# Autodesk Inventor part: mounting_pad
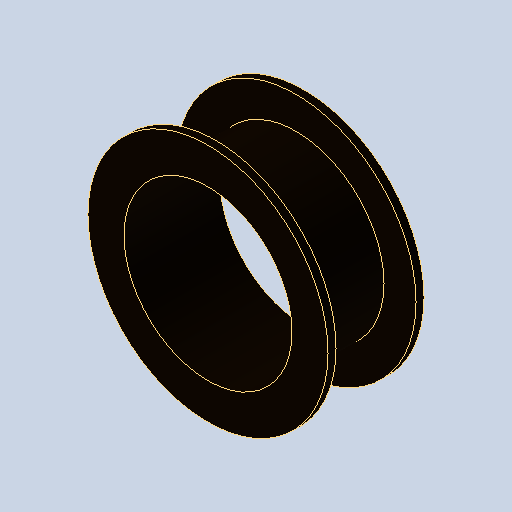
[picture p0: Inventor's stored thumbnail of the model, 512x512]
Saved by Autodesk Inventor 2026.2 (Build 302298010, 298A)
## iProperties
Created: 2026-10
Part Number: mounting_pad
Material: Générique
Document SubType Name: Modeling
Designer: mel
Density: 1 g/cm^3
Appearance: Par défaut
Author: mel
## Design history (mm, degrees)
feature "Base1"
node "Solide1"
